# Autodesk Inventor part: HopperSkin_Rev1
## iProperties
Created: 2009-01
Part Number: HopperSkin_Rev1
Document SubType Name: Modeling
Designer: claivier
Material: Résine thermoplastique
Norme de conversion: STEP AP214IS
Nom du fichier: HopperSkin_Rev1.STEP
Préprocesseur: SolidWorks 2008
Postprocesseur: Build: 344a, Release: 11 SP2 - Date: Fri 08/18/2006
Unités envoyées: INCHES
Incertitude: 1e-05
Author: claivier
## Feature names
1. Base1
